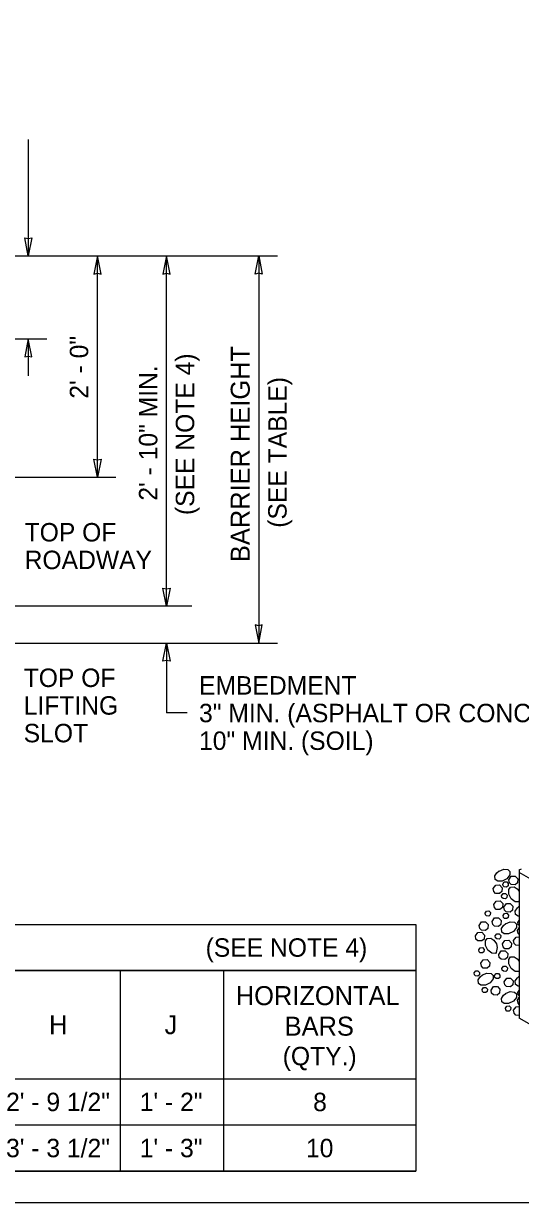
# Model space of a CAD drawing. Extents: x 99862 to 103680, y 99470 to 102076.
# Drawn here: x 101405 to 101837, y 100000 to 101023 of the extents above; entities that cross this region are included whole.
import ezdxf

# ---------------------------------------------------------------- set-up
doc = ezdxf.new("R2010")
doc.units = 0
for name, color, linetype in [('Level 1', 7, 'Continuous'), ('Level 15', 7, 'Continuous'), ('Level 16', 7, 'Continuous'), ('Level 2', 7, 'Continuous'), ('Level 20', 7, 'Continuous'), ('Level 40', 7, 'Continuous'), ('Level 7', 7, 'Continuous')]:
    doc.layers.add(name, color=color, linetype=linetype)

msp = doc.modelspace()

# ---------------------------------------------------------------- linework, layer by layer
at = {"layer": 'Level 1'}
msp.add_lwpolyline([(99862, 99999.5), (103151, 99999.5), (103151, 102075.5), (99862, 102075.5)], close=True, dxfattribs=at)
at = {"layer": 'Level 15'}
for p, q in [((101409.6, 100921.9), (101409.6, 100820.9)), ((101281.6, 100820.9), (101625.8, 100820.9)), ((101469.6, 100628.9), (101469.6, 100820.9)), ((101529.6, 100516.9), (101529.6, 100820.9)), ((101609.6, 100820.9), (101609.6, 100484.9)), ((101281.5, 100748.9), (101425.6, 100748.9)), ((101409.6, 100748.9), (101409.6, 100716.9)), ((101267.8, 100628.9), (101485.6, 100628.9)), ((101351.6, 100484.9), (101625.8, 100484.9)), ((101529.6, 100484.9), (101529.6, 100424.5)), ((101547.4, 100424.5), (101529.6, 100424.5))]:
    msp.add_line(p, q, dxfattribs=at)
for points in [[(101409.6, 100820.9), (101406.5, 100836.6), (101409.6, 100835.9), (101412.7, 100836.6)], [(101469.6, 100820.9), (101466.5, 100805.2), (101469.6, 100805.9), (101472.7, 100805.2)], [(101529.6, 100820.9), (101526.5, 100805.2), (101529.6, 100805.9), (101532.7, 100805.2)], [(101609.6, 100820.9), (101612.7, 100805.2), (101609.6, 100805.9), (101606.5, 100805.2)], [(101409.6, 100748.9), (101406.5, 100733.2), (101409.6, 100733.9), (101412.7, 100733.2)], [(101469.6, 100628.9), (101466.5, 100644.6), (101469.6, 100643.9), (101472.7, 100644.6)], [(101529.6, 100516.9), (101526.5, 100532.6), (101529.6, 100531.9), (101532.7, 100532.6)], [(101609.6, 100484.9), (101612.7, 100500.6), (101609.6, 100499.9), (101606.5, 100500.6)], [(101529.6, 100484.9), (101532.7, 100469.1), (101529.6, 100469.9), (101526.5, 100469.1)]]:
    msp.add_lwpolyline(points, close=True, dxfattribs=at)
at = {"layer": 'Level 16'}
msp.add_line((101551.6, 100516.9), (101333.5, 100516.9), dxfattribs=at)
at = {"layer": 'Level 2'}
for p, q in [((101835.7, 100288), (101837.7, 100289.1)), ((101835.7, 100288), (101835.7, 100285.7)), ((101835.7, 100285.7), (101835.7, 100159.4)), ((101845.7, 100280), (101835.7, 100285.7)), ((101879.5, 100134.2), (101835.7, 100159.4))]:
    msp.add_line(p, q, dxfattribs=at)
at = {"layer": 'Level 40'}
for p, q in [((101489.4, 100200.7), (101489.4, 100026.7)), ((101579.1, 100200.7), (101579.1, 100026.7)), ((100634.8, 100106.7), (101745.9, 100106.7)), ((100634.8, 100066.7), (101745.9, 100066.7)), ((100634.8, 100026.7), (101745.9, 100026.7))]:
    msp.add_line(p, q, dxfattribs=at)
for points in [[(100634.8, 100240.7), (101745.9, 100240.7), (101745.9, 100200.7), (100634.8, 100200.7)], [(100634.8, 100200.7), (101745.9, 100200.7), (101745.9, 100026.7), (100634.8, 100026.7)]]:
    msp.add_lwpolyline(points, close=True, dxfattribs=at)
at = {"layer": 'Level 7'}
for points in [[(101818.2, 100287.1), (101822.2, 100288.7), (101825.8, 100288.4), (101827.5, 100286.7), (101827.5, 100283.8), (101824.9, 100280.4), (101820.8, 100278.4), (101817, 100278.3), (101814.8, 100279.8), (101814.6, 100282.9), (101816.3, 100285.6), (101818.4, 100287.2)], [(101821.5, 100275.8), (101822.7, 100277.6), (101824.8, 100277.7), (101826.2, 100276.3), (101826, 100274.2), (101824.7, 100273.2), (101822.7, 100273.3), (101821.8, 100274.2), (101821.5, 100275.8)], [(101826.7, 100279.4), (101828.8, 100282.5), (101832.2, 100282.7), (101834.6, 100280.2), (101834.2, 100276.8), (101832.2, 100275), (101828.8, 100275.3), (101827.2, 100276.8), (101826.7, 100279.4)], [(101813.1, 100271.9), (101815.3, 100274.9), (101818.7, 100275.1), (101821, 100272.6), (101820.7, 100269.2), (101818.6, 100267.5), (101815.2, 100267.7), (101813.7, 100269.2), (101813.1, 100271.9)], [(101820.4, 100265.7), (101821.7, 100267.5), (101823.7, 100267.6), (101825.2, 100266.1), (101825, 100264.1), (101823.7, 100263), (101821.7, 100263.2), (101820.7, 100264.1), (101820.4, 100265.7)], [(101835.7, 100261.1), (101835, 100260.4), (101832.1, 100260.4), (101828.7, 100263.1), (101826.7, 100267.1), (101826.6, 100271), (101828.1, 100273.1), (101831.2, 100273.3), (101833.9, 100271.6), (101835.5, 100269.6)], [(101835.4, 100269.7), (101835.7, 100269)], [(101813.6, 100258), (101815.7, 100261), (101819.1, 100261.2), (101821.4, 100258.8), (101821.1, 100255.3), (101819, 100253.6), (101815.6, 100253.8), (101814.1, 100255.4), (101813.6, 100258)], [(101822.4, 100255.8), (101824.5, 100258.8), (101827.9, 100259), (101830.2, 100256.6), (101829.9, 100253.2), (101827.8, 100251.4), (101824.4, 100251.7), (101822.9, 100253.2), (101822.4, 100255.8)], [(101835.7, 100247.8), (101834.7, 100247.8), (101832.5, 100249.3), (101832.3, 100252.4), (101834.1, 100255.1), (101835.7, 100256.5)], [(101806.1, 100250.5), (101807.4, 100252.4), (101809.4, 100252.5), (101810.8, 100251), (101810.6, 100249), (101809.3, 100247.9), (101807.3, 100248.1), (101806.4, 100249), (101806.1, 100250.5)], [(101812.2, 100243.3), (101814.3, 100246.4), (101817.7, 100246.5), (101820, 100244.1), (101819.7, 100240.7), (101817.6, 100238.9), (101814.3, 100239.2), (101812.7, 100240.7), (101812.2, 100243.3)], [(101821.7, 100248.4), (101823, 100250.3), (101825, 100250.4), (101826.4, 100248.9), (101826.2, 100246.9), (101825, 100245.8), (101823, 100246), (101822, 100246.9), (101821.7, 100248.4)], [(101800.9, 100239.9), (101803, 100243), (101806.4, 100243.1), (101808.8, 100240.7), (101808.4, 100237.3), (101806.4, 100235.5), (101803, 100235.8), (101801.4, 100237.3), (101800.9, 100239.9)], [(101823.9, 100241.4), (101827.9, 100243), (101831.6, 100242.7), (101833.3, 100241), (101833.2, 100238.1), (101830.6, 100234.7), (101826.5, 100232.7), (101822.7, 100232.6), (101820.6, 100234.1), (101820.4, 100237.2), (101822.1, 100239.9), (101824.1, 100241.5)], [(101834.2, 100235.6), (101835.7, 100237.8)], [(101834.4, 100242.3), (101835.7, 100244.1), (101835.7, 100244.1)], [(101835.7, 100239.8), (101835.6, 100239.8), (101834.7, 100240.7), (101834.4, 100242.3)], [(101797.6, 100230.8), (101799.8, 100233.8), (101803.1, 100234), (101805.5, 100231.5), (101805.2, 100228.1), (101803.1, 100226.4), (101799.7, 100226.6), (101798.1, 100228.1), (101797.6, 100230.8)], [(101815.7, 100216.3), (101815, 100215.6), (101811.8, 100215.9), (101808.5, 100218.5), (101806.4, 100222.6), (101806.4, 100226.4), (101807.9, 100228.6), (101811, 100228.8), (101813.7, 100227), (101816, 100224), (101816.6, 100220.8), (101815.7, 100216.3)], [(101814.9, 100230.8), (101816.2, 100232.6), (101818.2, 100232.7), (101819.7, 100231.2), (101819.5, 100229.2), (101818.2, 100228.1), (101816.2, 100228.3), (101815.2, 100229.2), (101814.9, 100230.8)], [(101821.2, 100223.8), (101823.3, 100226.9), (101826.7, 100227.1), (101829, 100224.6), (101828.7, 100221.2), (101826.6, 100219.5), (101823.2, 100219.7), (101821.7, 100221.2), (101821.2, 100223.8)], [(101830.8, 100226.8), (101832.9, 100229.8), (101835.7, 100230)], [(101835.7, 100222.4), (101832.8, 100222.7), (101831.3, 100224.2), (101830.8, 100226.8)], [(101835.7, 100232.1), (101834.7, 100233), (101834.2, 100235.6)], [(101800.5, 100218.7), (101801.8, 100220.5), (101803.8, 100220.6), (101805.2, 100219.1), (101805, 100217.1), (101803.8, 100216), (101801.7, 100216.2), (101800.8, 100217.1), (101800.5, 100218.7)], [(101817.9, 100214.7), (101820, 100217.7), (101823.4, 100217.9), (101825.7, 100215.4), (101825.4, 100212), (101823.3, 100210.3), (101820, 100210.5), (101818.4, 100212), (101817.9, 100214.7)], [(101802.4, 100207), (101804.5, 100210.1), (101807.9, 100210.3), (101810.3, 100207.8), (101809.9, 100204.4), (101807.8, 100202.7), (101804.5, 100202.9), (101802.9, 100204.4), (101802.4, 100207)], [(101835.7, 100200.5), (101835, 100199.8), (101832.1, 100199.8), (101828.7, 100202.4), (101826.7, 100206.5), (101826.6, 100210.3), (101828.1, 100212.5), (101831.2, 100212.7), (101833.9, 100211), (101835.5, 100208.9)], [(101835.4, 100209.1), (101835.7, 100208.3)], [(101796.6, 100198.6), (101797.9, 100200.4), (101799.9, 100200.5), (101801.3, 100199), (101801.1, 100197), (101799.8, 100195.9), (101797.8, 100196.1), (101796.9, 100197), (101796.6, 100198.6)], [(101803.7, 100196.9), (101807.7, 100198.5), (101811.3, 100198.1), (101813.1, 100196.5), (101813, 100193.5), (101810.4, 100190.2), (101806.3, 100188.1), (101802.5, 100188.1), (101800.3, 100189.6), (101800.1, 100192.7), (101801.9, 100195.4), (101803.9, 100197)], [(101814.3, 100196.3), (101815.6, 100198.2), (101817.6, 100198.3), (101819, 100196.8), (101818.8, 100194.8), (101817.6, 100193.7), (101815.6, 100193.9), (101814.6, 100194.8), (101814.3, 100196.3)], [(101820.7, 100202.6), (101822, 100204.4), (101824, 100204.5), (101825.5, 100203.1), (101825.2, 100201), (101824, 100200), (101822, 100200.1), (101821, 100201), (101820.7, 100202.6)], [(101835.7, 100187.2), (101834.7, 100187.2), (101832.5, 100188.7), (101832.3, 100191.8), (101834.1, 100194.5), (101835.7, 100195.8)], [(101803.4, 100184.2), (101804.7, 100186), (101806.7, 100186.1), (101808.2, 100184.7), (101807.9, 100182.6), (101806.7, 100181.6), (101804.7, 100181.7), (101803.7, 100182.6), (101803.4, 100184.2)], [(101811.2, 100183.8), (101813.3, 100186.8), (101816.7, 100187), (101819, 100184.5), (101818.7, 100181.1), (101816.6, 100179.4), (101813.3, 100179.6), (101811.7, 100181.2), (101811.2, 100183.8)], [(101822.6, 100191), (101824.8, 100194), (101828.1, 100194.2), (101830.5, 100191.7), (101830.2, 100188.3), (101828.1, 100186.6), (101824.7, 100186.8), (101823.1, 100188.3), (101822.6, 100191)], [(101823.9, 100180.8), (101827.9, 100182.4), (101831.6, 100182.1), (101833.3, 100180.4), (101833.2, 100177.4), (101830.6, 100174.1), (101826.5, 100172), (101822.7, 100172), (101820.6, 100173.5), (101820.4, 100176.6), (101822.1, 100179.3), (101824.1, 100180.9)], [(101834.2, 100175), (101835.7, 100177.2)], [(101835.7, 100171.4), (101834.7, 100172.4), (101834.2, 100175)], [(101834.4, 100181.7), (101835.7, 100183.5), (101835.7, 100183.5)], [(101835.7, 100179.2), (101835.6, 100179.2), (101834.7, 100180.1), (101834.4, 100181.7)], [(101823.7, 100168.1), (101824.9, 100169.9), (101827, 100170), (101828.4, 100168.6), (101828.2, 100166.5), (101826.9, 100165.5), (101824.9, 100165.6), (101824, 100166.5), (101823.7, 100168.1)], [(101830.8, 100166.2), (101832.9, 100169.2), (101835.7, 100169.4)], [(101835.7, 100161.8), (101832.8, 100162), (101831.3, 100163.6), (101830.8, 100166.2)]]:
    msp.add_lwpolyline(points, dxfattribs=at)

# ---------------------------------------------------------------- texts
at = {"layer": 'Level 15'}
for s, p in [('HORIZONTAL', (101589.7, 100170.7)), ('H', (101427.6, 100145.5)), ('J', (101527.9, 100145.5)), ('BARS', (101632.1, 100144.2))]:
    msp.add_text(s, height=16.5, dxfattribs=at).set_placement(p)
at = {"layer": 'Level 20'}
for s, height, p in [('2\' - 0"', 16, (101461.6, 100697)), ('BARRIER HEIGHT', 16.5, (101601.8, 100555.2)), ('(SEE NOTE 4)', 16, (101553.6, 100596)), ('2\' - 10" MIN.', 16, (101521.6, 100608.5)), ('(SEE TABLE)', 16, (101633.8, 100585))]:
    msp.add_text(s, height=height, rotation=90, dxfattribs=at).set_placement(p)
for s, p in [('TOP OF', (101406.4, 100573.1)), ('ROADWAY', (101406.4, 100549.1)), ('TOP OF ', (101405.6, 100446.8)), ('EMBEDMENT', (101557.8, 100440.2)), ('LIFTING ', (101405.6, 100422.8)), ('3" MIN. (ASPHALT OR CONCRETE)', (101557.8, 100416.2)), ('SLOT', (101405.6, 100398.8)), ('10" MIN. (SOIL)', (101557.8, 100392.2)), ('(SEE NOTE 4)', (101563.5, 100212.7)), ('(QTY.)', (101630.4, 100118.5)), ('2\' - 9 1/2"', (101390.3, 100078.7)), ('1\' - 2"', (101506.3, 100078.7)), ('8', (101656.8, 100078.7)), ('3\' - 3 1/2"', (101390.3, 100038.7)), ('1\' - 3"', (101506.3, 100038.7)), ('10', (101650.6, 100038.7))]:
    msp.add_text(s, height=16, dxfattribs=at).set_placement(p)

doc.saveas('drawing.dxf')
